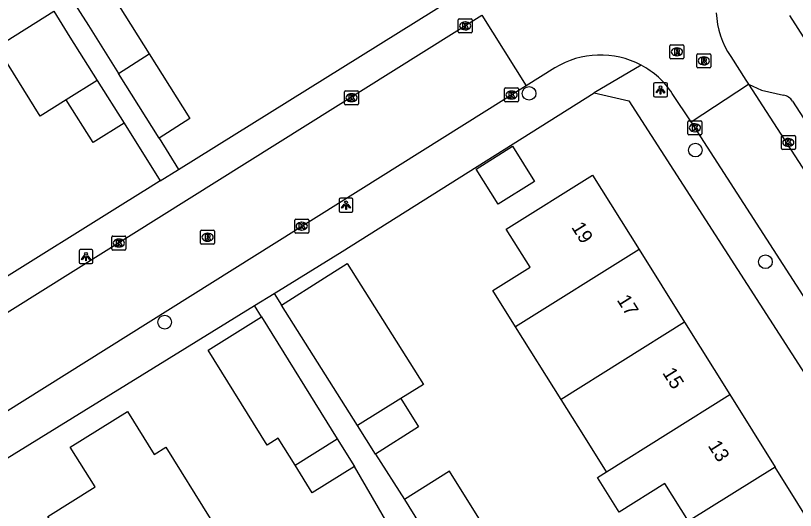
# Model space of a CAD drawing. Extents: x 159353 to 160616, y 385893 to 387321.
# Drawn here: x 159751.8 to 159807.5, y 386210.6 to 386245.9 of the extents above; entities that cross this region are included whole.
import ezdxf

# ---------------------------------------------------------------- set-up
doc = ezdxf.new("R2010")
doc.units = 0
for name, color, linetype in [('IMGEO_Boom', 7, 'Continuous'), ('IMGEO_Kolk', 7, 'Continuous'), ('IMGEO_Lichtpunt', 7, 'Continuous'), ('IMGEO_Pand', 7, 'Continuous'), ('IMGEO_Pand_nummerreeks', 7, 'Continuous'), ('IMGEO_Rijbaan_lokaal_open', 7, 'Continuous'), ('IMGEO_Rioolput', 7, 'Continuous'), ('IMGEO_Voetpad_open', 7, 'Continuous')]:
    doc.layers.add(name, color=color, linetype=linetype)

msp = doc.modelspace()

# ---------------------------------------------------------------- linework, layer by layer
at = {"layer": 'IMGEO_Boom'}
for centre in [(159788.517, 386240.338), (159800.399, 386236.283), (159805.403, 386228.315), (159762.478, 386223.997)]:
    msp.add_circle(centre, 0.489, dxfattribs=at)
at = {"layer": 'IMGEO_Kolk'}
for p, q in [((159783.454, 386244.73), (159783.454, 386245.582)), ((159783.529, 386245.656), (159784.381, 386245.656)), ((159783.942, 386245.436), (159783.967, 386245.436)), ((159784.455, 386245.582), (159784.455, 386244.73)), ((159783.965, 386244.876), (159783.94, 386244.876)), ((159784.381, 386244.656), (159783.529, 386244.656)), ((159775.332, 386239.601), (159775.332, 386240.453)), ((159775.407, 386240.527), (159776.259, 386240.527)), ((159775.82, 386240.307), (159775.845, 386240.307)), ((159776.333, 386240.453), (159776.333, 386239.601)), ((159786.766, 386239.797), (159786.766, 386240.649)), ((159786.841, 386240.723), (159787.693, 386240.723)), ((159787.254, 386240.503), (159787.279, 386240.503)), ((159787.767, 386240.649), (159787.767, 386239.797)), ((159775.843, 386239.747), (159775.818, 386239.747)), ((159787.693, 386239.723), (159786.841, 386239.723)), ((159787.277, 386239.943), (159787.252, 386239.943)), ((159776.259, 386239.527), (159775.407, 386239.527)), ((159799.866, 386237.453), (159799.866, 386238.305)), ((159799.941, 386238.379), (159800.793, 386238.379)), ((159800.354, 386238.159), (159800.379, 386238.159)), ((159800.867, 386238.305), (159800.867, 386237.453)), ((159800.377, 386237.599), (159800.352, 386237.599)), ((159800.793, 386237.379), (159799.941, 386237.379)), ((159806.546, 386236.406), (159806.546, 386237.258)), ((159806.621, 386237.332), (159807.473, 386237.332)), ((159807.034, 386237.112), (159807.059, 386237.112)), ((159807.547, 386237.258), (159807.547, 386236.406)), ((159807.057, 386236.552), (159807.032, 386236.552)), ((159807.473, 386236.332), (159806.621, 386236.332)), ((159771.847, 386231.355), (159772.699, 386231.355)), ((159771.772, 386230.429), (159771.772, 386231.281)), ((159772.26, 386231.135), (159772.285, 386231.135)), ((159772.773, 386231.281), (159772.773, 386230.429)), ((159772.699, 386230.355), (159771.847, 386230.355)), ((159772.283, 386230.575), (159772.258, 386230.575)), ((159758.705, 386229.223), (159758.705, 386230.075)), ((159758.78, 386230.149), (159759.632, 386230.149)), ((159759.193, 386229.929), (159759.218, 386229.929)), ((159759.706, 386230.075), (159759.706, 386229.223)), ((159759.632, 386229.149), (159758.78, 386229.149)), ((159759.216, 386229.369), (159759.191, 386229.369))]:
    msp.add_line(p, q, dxfattribs=at)
for points in [[(159783.454, 386244.73), (159783.454, 386245.582)], [(159783.529, 386245.656), (159784.381, 386245.656)], [(159783.775, 386245.356), (159783.898, 386245.356), (159783.898, 386245.205), (159784.028, 386245.356), (159784.192, 386245.356), (159784.046, 386245.205), (159784.199, 386244.956), (159784.047, 386244.956), (159783.962, 386245.12), (159783.898, 386245.053), (159783.898, 386244.956), (159783.775, 386244.956), (159783.775, 386245.356)], [(159784.455, 386245.582), (159784.455, 386244.73)], [(159784.381, 386244.656), (159783.529, 386244.656)], [(159775.332, 386239.601), (159775.332, 386240.453)], [(159775.407, 386240.527), (159776.259, 386240.527)], [(159776.333, 386240.453), (159776.333, 386239.601)], [(159786.766, 386239.797), (159786.766, 386240.649)], [(159786.841, 386240.723), (159787.693, 386240.723)], [(159787.087, 386240.423), (159787.21, 386240.423), (159787.21, 386240.272), (159787.34, 386240.423), (159787.504, 386240.423), (159787.358, 386240.272), (159787.511, 386240.023), (159787.359, 386240.023), (159787.274, 386240.187), (159787.21, 386240.12), (159787.21, 386240.023), (159787.087, 386240.023), (159787.087, 386240.423)], [(159787.767, 386240.649), (159787.767, 386239.797)], [(159775.653, 386240.227), (159775.776, 386240.227), (159775.776, 386240.076), (159775.906, 386240.227), (159776.07, 386240.227), (159775.924, 386240.076), (159776.077, 386239.827), (159775.925, 386239.827), (159775.84, 386239.991), (159775.776, 386239.924), (159775.776, 386239.827), (159775.653, 386239.827), (159775.653, 386240.227)], [(159787.693, 386239.723), (159786.841, 386239.723)], [(159776.259, 386239.527), (159775.407, 386239.527)], [(159799.866, 386237.453), (159799.866, 386238.305)], [(159799.941, 386238.379), (159800.793, 386238.379)], [(159800.187, 386238.079), (159800.31, 386238.079), (159800.31, 386237.928), (159800.44, 386238.079), (159800.604, 386238.079), (159800.458, 386237.928), (159800.611, 386237.679), (159800.459, 386237.679), (159800.374, 386237.843), (159800.31, 386237.776), (159800.31, 386237.679), (159800.187, 386237.679), (159800.187, 386238.079)], [(159800.867, 386238.305), (159800.867, 386237.453)], [(159800.793, 386237.379), (159799.941, 386237.379)], [(159806.546, 386236.406), (159806.546, 386237.258)], [(159806.621, 386237.332), (159807.473, 386237.332)], [(159806.867, 386237.032), (159806.99, 386237.032), (159806.99, 386236.881), (159807.12, 386237.032), (159807.284, 386237.032), (159807.138, 386236.881), (159807.291, 386236.632), (159807.139, 386236.632), (159807.054, 386236.796), (159806.99, 386236.729), (159806.99, 386236.632), (159806.867, 386236.632), (159806.867, 386237.032)], [(159807.547, 386237.258), (159807.547, 386236.406)], [(159807.473, 386236.332), (159806.621, 386236.332)], [(159771.847, 386231.355), (159772.699, 386231.355)], [(159771.772, 386230.429), (159771.772, 386231.281)], [(159772.093, 386231.055), (159772.216, 386231.055), (159772.216, 386230.904), (159772.346, 386231.055), (159772.51, 386231.055), (159772.364, 386230.904), (159772.517, 386230.655), (159772.365, 386230.655), (159772.28, 386230.819), (159772.216, 386230.752), (159772.216, 386230.655), (159772.093, 386230.655), (159772.093, 386231.055)], [(159772.773, 386231.281), (159772.773, 386230.429)], [(159772.699, 386230.355), (159771.847, 386230.355)], [(159758.705, 386229.223), (159758.705, 386230.075)], [(159758.78, 386230.149), (159759.632, 386230.149)], [(159759.026, 386229.849), (159759.149, 386229.849), (159759.149, 386229.698), (159759.279, 386229.849), (159759.443, 386229.849), (159759.297, 386229.698), (159759.45, 386229.449), (159759.298, 386229.449), (159759.213, 386229.613), (159759.149, 386229.546), (159759.149, 386229.449), (159759.026, 386229.449), (159759.026, 386229.849)], [(159759.706, 386230.075), (159759.706, 386229.223)], [(159759.632, 386229.149), (159758.78, 386229.149)]]:
    msp.add_lwpolyline(points, dxfattribs=at)
for centre, start, end in [((159783.531, 386245.58), 91.552, 178.448), ((159783.531, 386245.58), 91.552, 178.448), ((159784.379, 386245.58), 1.552, 88.448), ((159784.379, 386245.58), 1.552, 88.448), ((159783.531, 386244.732), 181.552, 268.448), ((159783.531, 386244.732), 181.552, 268.448), ((159784.379, 386244.732), 271.552, 358.448), ((159784.379, 386244.732), 271.552, 358.448), ((159775.409, 386240.451), 91.552, 178.448), ((159775.409, 386240.451), 91.552, 178.448), ((159776.257, 386240.451), 1.552, 88.448), ((159776.257, 386240.451), 1.552, 88.448), ((159786.843, 386240.647), 91.552, 178.448), ((159786.843, 386240.647), 91.552, 178.448), ((159787.691, 386240.647), 1.552, 88.448), ((159787.691, 386240.647), 1.552, 88.448), ((159786.843, 386239.799), 181.552, 268.448), ((159786.843, 386239.799), 181.552, 268.448), ((159787.691, 386239.799), 271.552, 358.448), ((159787.691, 386239.799), 271.552, 358.448), ((159775.409, 386239.603), 181.552, 268.448), ((159775.409, 386239.603), 181.552, 268.448), ((159776.257, 386239.603), 271.552, 358.448), ((159776.257, 386239.603), 271.552, 358.448), ((159799.943, 386238.303), 91.552, 178.448), ((159799.943, 386238.303), 91.552, 178.448), ((159800.791, 386238.303), 1.552, 88.448), ((159800.791, 386238.303), 1.552, 88.448), ((159799.943, 386237.455), 181.552, 268.448), ((159799.943, 386237.455), 181.552, 268.448), ((159800.791, 386237.455), 271.552, 358.448), ((159800.791, 386237.455), 271.552, 358.448), ((159806.623, 386237.256), 91.552, 178.448), ((159806.623, 386237.256), 91.552, 178.448), ((159807.471, 386237.256), 1.552, 88.448), ((159807.471, 386237.256), 1.552, 88.448), ((159806.623, 386236.408), 181.552, 268.448), ((159806.623, 386236.408), 181.552, 268.448), ((159807.471, 386236.408), 271.552, 358.448), ((159807.471, 386236.408), 271.552, 358.448), ((159771.849, 386231.279), 91.552, 178.448), ((159771.849, 386231.279), 91.552, 178.448), ((159772.697, 386231.279), 1.552, 88.448), ((159772.697, 386231.279), 1.552, 88.448), ((159771.849, 386230.431), 181.552, 268.448), ((159771.849, 386230.431), 181.552, 268.448), ((159772.697, 386230.431), 271.552, 358.448), ((159772.697, 386230.431), 271.552, 358.448), ((159758.782, 386230.073), 91.552, 178.448), ((159758.782, 386230.073), 91.552, 178.448), ((159759.63, 386230.073), 1.552, 88.448), ((159759.63, 386230.073), 1.552, 88.448), ((159758.782, 386229.225), 181.552, 268.448), ((159758.782, 386229.225), 181.552, 268.448), ((159759.63, 386229.225), 271.552, 358.448), ((159759.63, 386229.225), 271.552, 358.448)]:
    msp.add_arc(centre, 0.0765, start, end, dxfattribs=at)
for centre, major_axis, ratio, start_param, end_param in [((159783.941, 386245.156), (-0.387, 0.002), 0.722429, 4.712389, 7.853982), ((159783.966, 386245.156), (-0.39, 0.002), 0.717154, 1.570796, 4.712389), ((159775.819, 386240.027), (-0.387, 0.002), 0.722429, 4.712389, 7.853982), ((159775.844, 386240.027), (-0.39, 0.002), 0.717154, 1.570796, 4.712389), ((159787.253, 386240.223), (-0.387, 0.002), 0.722429, 4.712389, 7.853982), ((159787.278, 386240.223), (-0.39, 0.002), 0.717154, 1.570796, 4.712389), ((159800.353, 386237.879), (-0.387, 0.002), 0.722429, 4.712389, 7.853982), ((159800.378, 386237.879), (-0.39, 0.002), 0.717154, 1.570796, 4.712389), ((159807.033, 386236.832), (-0.387, 0.002), 0.722429, 4.712389, 7.853982), ((159807.058, 386236.832), (-0.39, 0.002), 0.717154, 1.570796, 4.712389), ((159772.259, 386230.855), (-0.387, 0.002), 0.722429, 4.712389, 7.853982), ((159772.284, 386230.855), (-0.39, 0.002), 0.717154, 1.570796, 4.712389), ((159759.192, 386229.649), (-0.387, 0.002), 0.722429, 4.712389, 7.853982), ((159759.217, 386229.649), (-0.39, 0.002), 0.717154, 1.570796, 4.712389)]:
    msp.add_ellipse(centre, major_axis=major_axis, ratio=ratio, start_param=start_param, end_param=end_param, dxfattribs=at)
at = {"layer": 'IMGEO_Lichtpunt'}
for p, q in [((159797.405, 386240.989), (159797.405, 386240.182)), ((159797.405, 386240.989), (159797.405, 386240.182)), ((159798.307, 386241.084), (159797.499, 386241.084)), ((159798.307, 386241.084), (159797.499, 386241.084)), ((159798.401, 386240.182), (159798.401, 386240.989)), ((159798.401, 386240.182), (159798.401, 386240.989)), ((159797.499, 386240.088), (159798.307, 386240.088)), ((159797.499, 386240.088), (159798.307, 386240.088)), ((159774.938, 386232.756), (159774.938, 386231.949)), ((159774.938, 386232.756), (159774.938, 386231.949)), ((159775.84, 386232.851), (159775.032, 386232.851)), ((159775.84, 386232.851), (159775.032, 386232.851)), ((159775.934, 386231.949), (159775.934, 386232.756)), ((159775.934, 386231.949), (159775.934, 386232.756)), ((159775.032, 386231.855), (159775.84, 386231.855)), ((159775.032, 386231.855), (159775.84, 386231.855)), ((159757.258, 386229.177), (159756.45, 386229.177)), ((159757.258, 386229.177), (159756.45, 386229.177)), ((159756.356, 386229.082), (159756.356, 386228.275)), ((159756.356, 386229.082), (159756.356, 386228.275)), ((159757.352, 386228.275), (159757.352, 386229.082)), ((159757.352, 386228.275), (159757.352, 386229.082)), ((159756.45, 386228.181), (159757.258, 386228.181)), ((159756.45, 386228.181), (159757.258, 386228.181))]:
    msp.add_line(p, q, dxfattribs=at)
for points in [[(159797.779, 386240.653), (159797.818, 386240.625), (159797.63, 386240.363), (159797.592, 386240.39), (159797.779, 386240.653)], [(159797.881, 386240.605), (159797.928, 386240.605), (159797.928, 386240.283), (159797.881, 386240.283), (159797.881, 386240.605)], [(159797.991, 386240.625), (159798.029, 386240.652), (159798.216, 386240.39), (159798.177, 386240.362), (159797.991, 386240.625)], [(159775.312, 386232.42), (159775.351, 386232.392), (159775.163, 386232.13), (159775.125, 386232.157), (159775.312, 386232.42)], [(159775.414, 386232.372), (159775.461, 386232.372), (159775.461, 386232.05), (159775.414, 386232.05), (159775.414, 386232.372)], [(159775.524, 386232.392), (159775.562, 386232.419), (159775.749, 386232.157), (159775.71, 386232.129), (159775.524, 386232.392)], [(159756.73, 386228.746), (159756.769, 386228.718), (159756.581, 386228.456), (159756.543, 386228.483), (159756.73, 386228.746)], [(159756.832, 386228.698), (159756.879, 386228.698), (159756.879, 386228.376), (159756.832, 386228.376), (159756.832, 386228.698)], [(159756.942, 386228.718), (159756.98, 386228.745), (159757.167, 386228.483), (159757.128, 386228.455), (159756.942, 386228.718)]]:
    msp.add_lwpolyline(points, dxfattribs=at)
for centre in [(159797.904, 386240.787), (159775.437, 386232.554), (159756.855, 386228.88)]:
    msp.add_circle(centre, 0.0994, dxfattribs=at)
for centre, start, end in [((159797.499, 386240.989), 90, 180), ((159797.499, 386240.989), 90, 180), ((159798.307, 386240.989), 0, 90), ((159798.307, 386240.989), 0, 90), ((159797.499, 386240.182), 180, 270), ((159797.499, 386240.182), 180, 270), ((159798.307, 386240.182), 270, 0), ((159798.307, 386240.182), 270, 360), ((159775.032, 386232.756), 90, 180), ((159775.032, 386232.756), 90, 180), ((159775.84, 386232.756), 0, 90), ((159775.84, 386232.756), 0, 90), ((159775.032, 386231.949), 180, 270), ((159775.032, 386231.949), 180, 270), ((159775.84, 386231.949), 270, 0), ((159775.84, 386231.949), 270, 360), ((159756.45, 386229.082), 90, 180), ((159756.45, 386229.082), 90, 180), ((159757.258, 386229.082), 0, 90), ((159757.258, 386229.082), 0, 90), ((159756.45, 386228.275), 180, 270), ((159756.45, 386228.275), 180, 270), ((159757.258, 386228.275), 270, 0), ((159757.258, 386228.275), 270, 360)]:
    msp.add_arc(centre, 0.0946, start, end, dxfattribs=at)
at = {"layer": 'IMGEO_Pand'}
for points in [[(159755.843, 386247.069), (159758.046, 386248.452), (159759.237, 386246.555), (159761.363, 386243.168)], [(159755.843, 386247.069), (159757.029, 386245.181), (159759.177, 386241.76)], [(159755.439, 386239.875), (159753.588, 386238.717), (159750.483, 386243.658), (159754.552, 386246.204)], [(159754.552, 386246.204), (159755.71, 386244.361), (159757.657, 386241.262)], [(159759.177, 386241.76), (159761.363, 386243.168)], [(159761.363, 386243.168), (159764.269, 386238.54), (159762.083, 386237.131)], [(159762.083, 386237.131), (159759.177, 386241.76)], [(159757.657, 386241.262), (159755.439, 386239.875)], [(159757.657, 386241.262), (159759.573, 386238.214)], [(159759.573, 386238.214), (159757.358, 386236.822), (159755.439, 386239.875)], [(159786.314, 386232.413), (159784.737, 386234.935), (159787.33, 386236.556), (159788.907, 386234.034), (159786.314, 386232.413)], [(159787.55, 386223.668), (159785.923, 386226.265), (159788.59, 386227.93), (159786.891, 386230.641), (159793.055, 386234.495), (159796.375, 386229.186)], [(159796.375, 386229.186), (159787.55, 386223.668)], [(159796.375, 386229.186), (159799.617, 386224.003)], [(159770.825, 386225.212), (159773.906, 386227.157), (159775.527, 386228.18), (159780.971, 386219.554), (159779.346, 386218.538)], [(159776.257, 386216.607), (159770.825, 386225.212)], [(159771.798, 386213.774), (159770.589, 386215.714), (159769.792, 386215.217), (159765.574, 386221.988), (159769.393, 386224.367)], [(159769.393, 386224.367), (159774.815, 386215.663)], [(159790.799, 386218.484), (159787.55, 386223.668)], [(159799.617, 386224.003), (159790.799, 386218.484)], [(159799.617, 386224.003), (159802.857, 386218.822)], [(159779.346, 386218.538), (159776.257, 386216.607)], [(159779.346, 386218.538), (159780.625, 386216.512), (159777.544, 386214.567)], [(159794.046, 386213.312), (159802.857, 386218.822)], [(159802.857, 386218.822), (159806.098, 386213.64)], [(159794.046, 386213.312), (159792.427, 386215.909), (159790.799, 386218.484)], [(159757.464, 386204.805), (159754.14, 386210.126), (159757.508, 386212.23), (159755.734, 386215.072), (159759.813, 386217.62), (159761.735, 386214.54), (159762.567, 386215.059), (159765.736, 386209.983)], [(159777.544, 386214.567), (159776.257, 386216.607)], [(159771.798, 386213.774), (159774.815, 386215.663)], [(159774.815, 386215.663), (159776.037, 386213.7)], [(159776.037, 386213.7), (159773.016, 386211.819), (159771.798, 386213.774)], [(159806.098, 386213.64), (159799.918, 386209.775)], [(159809.339, 386208.458), (159806.098, 386213.64)], [(159786.004, 386208.282), (159782.839, 386213.345), (159779.607, 386211.324)], [(159799.918, 386209.775), (159798.228, 386212.484), (159794.952, 386210.43), (159793.409, 386212.904), (159794.046, 386213.312)], [(159779.607, 386211.324), (159782.771, 386206.262)]]:
    msp.add_lwpolyline(points, dxfattribs=at)
at = {"layer": 'IMGEO_Rijbaan_lokaal_open'}
for points in [[(159743.302, 386219.747), (159785.144, 386245.916)], [(159785.144, 386245.916), (159788.312, 386240.88)], [(159802.932, 386242.97), (159804.007, 386241.283), (159804.207, 386241.004)], [(159790.369, 386242.15), (159788.312, 386240.88)], [(159788.312, 386240.88), (159746.461, 386214.673)], [(159800.096, 386238.294), (159804.207, 386241.004)], [(159800.096, 386238.294), (159798.749, 386240.336)]]:
    msp.add_lwpolyline(points, dxfattribs=at)
for centre, radius, start, end in [((159807.605, 386246.253), 5.711, 181.5999, 215.0939), ((159793.623, 386236.916), 6.163, 61.9432, 121.8732), ((159793.608, 386236.903), 6.182, 33.7335, 61.8756)]:
    msp.add_arc(centre, radius, start, end, dxfattribs=at)
at = {"layer": 'IMGEO_Rioolput'}
for p, q in [((159798.58, 386242.878), (159798.58, 386243.73)), ((159798.655, 386243.804), (159799.507, 386243.804)), ((159799.581, 386243.73), (159799.581, 386242.878)), ((159799.068, 386243.584), (159799.093, 386243.584)), ((159800.504, 386242.23), (159800.504, 386243.082)), ((159800.579, 386243.156), (159801.431, 386243.156)), ((159801.505, 386243.082), (159801.505, 386242.23)), ((159799.507, 386242.804), (159798.655, 386242.804)), ((159799.091, 386243.024), (159799.066, 386243.024)), ((159800.992, 386242.936), (159801.017, 386242.936)), ((159801.431, 386242.156), (159800.579, 386242.156)), ((159801.015, 386242.376), (159800.99, 386242.376)), ((159765.043, 386229.636), (159765.043, 386230.488)), ((159765.118, 386230.562), (159765.97, 386230.562)), ((159765.531, 386230.342), (159765.556, 386230.342)), ((159766.044, 386230.488), (159766.044, 386229.636)), ((159765.554, 386229.782), (159765.529, 386229.782)), ((159765.97, 386229.562), (159765.118, 386229.562))]:
    msp.add_line(p, q, dxfattribs=at)
for points in [[(159798.58, 386242.878), (159798.58, 386243.73)], [(159798.655, 386243.804), (159799.507, 386243.804)], [(159799.581, 386243.73), (159799.581, 386242.878)], [(159799.169, 386243.502), (159798.917, 386243.504), (159798.917, 386243.104)], [(159798.917, 386243.104), (159799.041, 386243.104), (159799.041, 386243.266), (159799.052, 386243.266)], [(159799.095, 386243.423), (159799.041, 386243.423), (159799.041, 386243.342)], [(159799.041, 386243.342), (159799.093, 386243.342)], [(159799.099, 386243.237), (159799.17, 386243.104), (159799.31, 386243.104), (159799.245, 386243.23)], [(159800.504, 386242.23), (159800.504, 386243.082)], [(159800.579, 386243.156), (159801.431, 386243.156)], [(159801.505, 386243.082), (159801.505, 386242.23)], [(159799.507, 386242.804), (159798.655, 386242.804)], [(159801.093, 386242.854), (159800.841, 386242.856), (159800.841, 386242.456)], [(159800.841, 386242.456), (159800.965, 386242.456), (159800.965, 386242.618), (159800.976, 386242.618)], [(159801.019, 386242.775), (159800.965, 386242.775), (159800.965, 386242.694)], [(159800.965, 386242.694), (159801.017, 386242.694)], [(159801.023, 386242.589), (159801.094, 386242.456), (159801.234, 386242.456), (159801.169, 386242.582)], [(159801.431, 386242.156), (159800.579, 386242.156)], [(159765.043, 386229.636), (159765.043, 386230.488)], [(159765.118, 386230.562), (159765.97, 386230.562)], [(159765.632, 386230.26), (159765.38, 386230.262), (159765.38, 386229.862)], [(159766.044, 386230.488), (159766.044, 386229.636)], [(159765.38, 386229.862), (159765.504, 386229.862), (159765.504, 386230.024), (159765.515, 386230.024)], [(159765.558, 386230.181), (159765.504, 386230.181), (159765.504, 386230.1)], [(159765.504, 386230.1), (159765.556, 386230.1)], [(159765.562, 386229.995), (159765.633, 386229.862), (159765.773, 386229.862), (159765.708, 386229.988)], [(159765.97, 386229.562), (159765.118, 386229.562)]]:
    msp.add_lwpolyline(points, dxfattribs=at)
for centre, radius, start, end in [((159798.657, 386243.728), 0.0765, 91.552, 178.448), ((159798.657, 386243.728), 0.0765, 91.552, 178.448), ((159799.505, 386243.728), 0.0765, 1.552, 88.448), ((159799.505, 386243.728), 0.0765, 1.552, 88.448), ((159799.051, 386243.213), 0.0533, 26.0293, 88.6989), ((159799.077, 386243.531), 0.19, 274.7715, 282.9687), ((159799.101, 386243.327), 0.0964, 77.0061, 93.1865), ((159799.115, 386243.384), 0.0378, 276.6634, 79.6772), ((159799.168, 386243.392), 0.109, 350.3612, 89.416), ((159799.166, 386243.392), 0.112, 277.5842, 350.9817), ((159799.15, 386243.177), 0.108, 29.5134, 73.7905), ((159800.581, 386243.08), 0.0765, 91.552, 178.448), ((159800.581, 386243.08), 0.0765, 91.552, 178.448), ((159801.429, 386243.08), 0.0765, 1.552, 88.448), ((159801.429, 386243.08), 0.0765, 1.552, 88.448), ((159798.657, 386242.88), 0.0765, 181.552, 268.448), ((159798.657, 386242.88), 0.0765, 181.552, 268.448), ((159799.505, 386242.88), 0.0765, 271.552, 358.448), ((159799.505, 386242.88), 0.0765, 271.552, 358.448), ((159800.975, 386242.565), 0.0533, 26.0293, 88.6989), ((159801.001, 386242.883), 0.19, 274.7715, 282.9687), ((159801.025, 386242.679), 0.0964, 77.0061, 93.1865), ((159801.039, 386242.736), 0.0378, 276.6634, 79.6772), ((159801.092, 386242.744), 0.109, 350.3612, 89.416), ((159801.09, 386242.744), 0.112, 277.5842, 350.9817), ((159801.074, 386242.529), 0.108, 29.5134, 73.7905), ((159800.581, 386242.232), 0.0765, 181.552, 268.448), ((159800.581, 386242.232), 0.0765, 181.552, 268.448), ((159801.429, 386242.232), 0.0765, 271.552, 358.448), ((159801.429, 386242.232), 0.0765, 271.552, 358.448), ((159765.12, 386230.486), 0.0765, 91.552, 178.448), ((159765.12, 386230.486), 0.0765, 91.552, 178.448), ((159765.631, 386230.15), 0.109, 350.3612, 89.416), ((159765.968, 386230.486), 0.0765, 1.552, 88.448), ((159765.968, 386230.486), 0.0765, 1.552, 88.448), ((159765.514, 386229.971), 0.0533, 26.0293, 88.6989), ((159765.54, 386230.289), 0.19, 274.7715, 282.9687), ((159765.564, 386230.085), 0.0964, 77.0061, 93.1865), ((159765.578, 386230.142), 0.0378, 276.6634, 79.6772), ((159765.629, 386230.15), 0.112, 277.5842, 350.9817), ((159765.613, 386229.935), 0.108, 29.5134, 73.7905), ((159765.12, 386229.638), 0.0765, 181.552, 268.448), ((159765.12, 386229.638), 0.0765, 181.552, 268.448), ((159765.968, 386229.638), 0.0765, 271.552, 358.448), ((159765.968, 386229.638), 0.0765, 271.552, 358.448)]:
    msp.add_arc(centre, radius, start, end, dxfattribs=at)
for centre, major_axis, ratio, start_param, end_param in [((159799.067, 386243.304), (-0.387, 0.002), 0.722429, 4.712389, 7.853982), ((159799.092, 386243.304), (-0.39, 0.002), 0.717154, 1.570796, 4.712389), ((159800.991, 386242.656), (-0.387, 0.002), 0.722429, 4.712389, 7.853982), ((159801.016, 386242.656), (-0.39, 0.002), 0.717154, 1.570796, 4.712389), ((159765.53, 386230.062), (-0.387, 0.002), 0.722429, 4.712389, 7.853982), ((159765.555, 386230.062), (-0.39, 0.002), 0.717154, 1.570796, 4.712389)]:
    msp.add_ellipse(centre, major_axis=major_axis, ratio=ratio, start_param=start_param, end_param=end_param, dxfattribs=at)
at = {"layer": 'IMGEO_Voetpad_open'}
for points in [[(159763.469, 386234.908), (159785.681, 386248.757), (159786.324, 386249.298), (159786.787, 386250)], [(159807.126, 386245.89), (159842.817, 386190.245)], [(159796.522, 386242.355), (159793.173, 386240.363)], [(159804.207, 386241.004), (159805.135, 386240.556), (159806.703, 386240.214)], [(159804.207, 386241.004), (159837.82, 386189.003)], [(159770.299, 386226.046), (159775.161, 386229.041), (159793.173, 386240.363)], [(159793.173, 386240.363), (159795.649, 386239.796), (159831.974, 386183.449)], [(159807.339, 386239.784), (159837.799, 386192.71)], [(159759.573, 386238.214), (159762.148, 386234.084)], [(159833.027, 386187.288), (159800.096, 386238.294)], [(159762.083, 386237.131), (159763.469, 386234.908)], [(159762.148, 386234.084), (159763.469, 386234.908)], [(159762.148, 386234.084), (159761.439, 386233.642), (159759.476, 386232.418), (159741.323, 386221.099)], [(159768.892, 386225.18), (159770.299, 386226.046)], [(159770.299, 386226.046), (159770.825, 386225.212)], [(159745.591, 386210.827), (159768.892, 386225.18)], [(159769.393, 386224.367), (159768.892, 386225.18)], [(159777.544, 386214.567), (159779.607, 386211.324)], [(159779.736, 386207.334), (159776.037, 386213.7)]]:
    msp.add_lwpolyline(points, dxfattribs=at)
msp.add_arc((159806.48, 386239.199), 1.039, 34.2588, 77.6159, dxfattribs=at)

# ---------------------------------------------------------------- texts
at = {"layer": 'IMGEO_Pand_nummerreeks'}
for s, p in [('19', (159791.51, 386230.78)), ('17', (159794.762, 386225.581)), ('15', (159798.014, 386220.381)), ('13', (159801.265, 386215.182))]:
    msp.add_text(s, height=1, rotation=302.0233, dxfattribs=at).set_placement(p)

doc.saveas('drawing.dxf')
